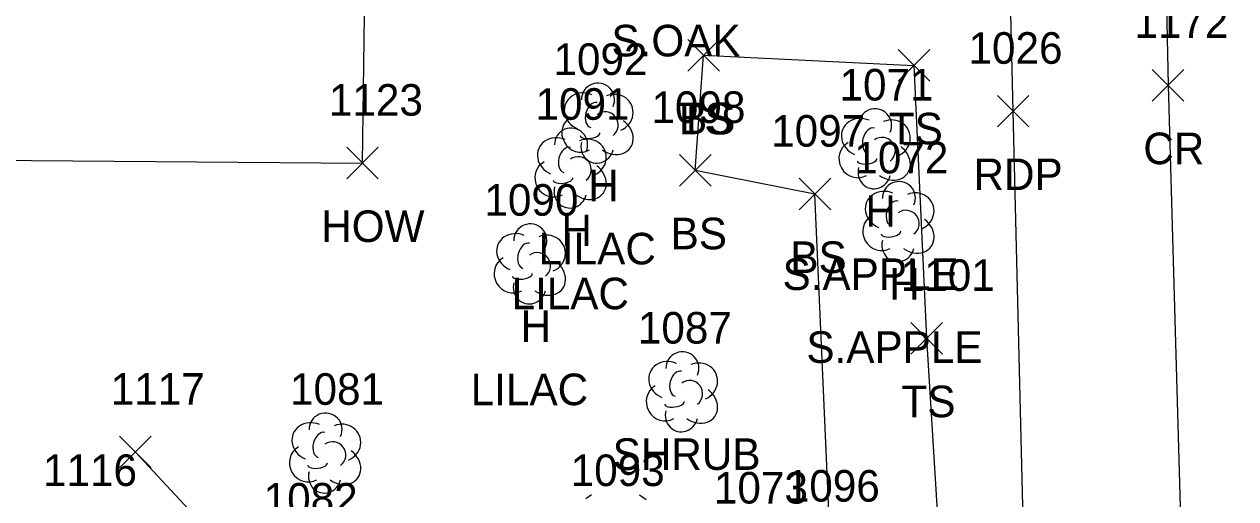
# Model space of a CAD drawing. Extents: x 1609623 to 1616187, y 756677 to 762826.
# Drawn here: x 1610552.4 to 1610629.1, y 761419.2 to 761449.2 of the extents above; entities that cross this region are included whole.
import ezdxf

# ---------------------------------------------------------------- set-up
doc = ezdxf.new("R2010")
doc.units = 0
for name, color, linetype in [('L_A', 7, 'Continuous'), ('L_C', 7, 'Continuous'), ('L_I', 7, 'Continuous'), ('L_TIC', 7, 'Continuous'), ('LBC', 7, 'Continuous'), ('LELB', 7, 'Continuous'), ('LSH', 7, 'Continuous'), ('LTC', 7, 'Continuous'), ('LTD', 7, 'Continuous'), ('P_A', 7, 'Continuous'), ('P_I', 7, 'Continuous'), ('P_TIC', 7, 'Continuous'), ('PET', 7, 'Continuous'), ('PRC', 7, 'Continuous')]:
    doc.layers.add(name, color=color, linetype=linetype)

msp = doc.modelspace()

# ---------------------------------------------------------------- linework, layer by layer
at = {"layer": 'L_TIC'}
for points in [[(1610594.408, 761446.245), (1610596.408, 761448.245)], [(1610596.408, 761446.245), (1610594.408, 761448.245)], [(1610594.408, 761446.245), (1610596.408, 761448.245)], [(1610596.408, 761446.245), (1610594.408, 761448.245)], [(1610607.722, 761445.603), (1610609.722, 761447.603)], [(1610609.722, 761445.603), (1610607.722, 761447.603)], [(1610572.816, 761439.42), (1610574.816, 761441.42)], [(1610574.816, 761439.42), (1610572.816, 761441.42)], [(1610593.878, 761438.959), (1610595.878, 761440.959)], [(1610595.878, 761438.959), (1610593.878, 761440.959)], [(1610601.455, 761437.458), (1610603.455, 761439.458)], [(1610603.455, 761437.458), (1610601.455, 761439.458)], [(1610608.524, 761428.323), (1610610.524, 761430.323)], [(1610610.524, 761428.323), (1610608.524, 761430.323)], [(1610558.441, 761421.114), (1610560.441, 761423.114)], [(1610560.441, 761421.114), (1610558.441, 761423.114)]]:
    msp.add_lwpolyline(points, dxfattribs=at)
at = {"layer": 'LBC'}
msp.add_lwpolyline([(1610544.984, 761440.641), (1610573.816, 761440.42), (1610574.182, 761466.993), (1610555.002, 761467.54), (1610555.534, 761478.683)], dxfattribs=at)
at = {"layer": 'LELB'}
for points in [[(1610595.408, 761447.245), (1610608.722, 761446.603), (1610609.524, 761429.323), (1610611.272, 761400.906), (1610611.999, 761372.747), (1610611.991, 761340.299), (1610612.489, 761301.493), (1610613.599, 761291.642), (1610617.432, 761248.111), (1610619.063, 761216.607), (1610613.007, 761244.85), (1610608.328, 761282.169), (1610599.672, 761300.772), (1610566.416, 761313.734)], [(1610596.168, 761387.633), (1610603.437, 761415.978), (1610602.455, 761438.458), (1610594.878, 761439.959), (1610595.408, 761447.245)], [(1610559.441, 761422.114), (1610573.999, 761406.454), (1610582.422, 761390.653)]]:
    msp.add_lwpolyline(points, dxfattribs=at)
at = {"layer": 'LSH'}
msp.add_line((1610594.018, 761425.986), (1610594.018, 761425.986), dxfattribs=at)
msp.add_line((1610594.018, 761425.986), (1610594.018, 761425.986), dxfattribs=at)
msp.add_arc((1610594.064, 761427.42), 1.047, 335.52715, 180.95627, dxfattribs=at)
for centre, major_axis, ratio, start_param, end_param in [((1610593.226, 761426.652), (1.21, -0.512), 0.895232, 1.570796, 4.712389), ((1610595.059, 761426.569), (-1.141, -0.483), 0.949671, 1.570796, 4.712389), ((1610593.809, 761426.444), (-0.208, -0.792), 0.645439, 3.141593, 6.283185), ((1610594.518, 761425.819), (-0.5, 0.667), 0.989748, 3.141593, 6.283185), ((1610592.934, 761425.277), (0.584, -1.042), 0.959034, 3.141593, 6.283185), ((1610595.018, 761425.153), (-1.09, 0.792), 0.841452, 1.570796, 4.712389), ((1610593.559, 761425.236), (-0.625, -0.083), 0.423636, 0, 3.141593), ((1610594.018, 761424.486), (0.265, 1.061), 0.942809, 1.570796, 4.712389)]:
    msp.add_ellipse(centre, major_axis=major_axis, ratio=ratio, start_param=start_param, end_param=end_param, dxfattribs=at)
at = {"layer": 'LTC'}
for p, q in [((1610587.961, 761419.171), (1610588.315, 761419.428)), ((1610591.359, 761419.411), (1610591.778, 761419.107))]:
    msp.add_line(p, q, dxfattribs=at)
at = {"layer": 'LTD'}
for p, q in [((1610588.674, 761443.001), (1610588.674, 761443.001)), ((1610588.674, 761443.001), (1610588.674, 761443.001)), ((1610606.214, 761441.381), (1610606.214, 761441.381)), ((1610606.214, 761441.381), (1610606.214, 761441.381)), ((1610586.972, 761440.16), (1610586.972, 761440.16)), ((1610586.972, 761440.16), (1610586.972, 761440.16)), ((1610607.722, 761436.764), (1610607.722, 761436.764)), ((1610607.722, 761436.764), (1610607.722, 761436.764)), ((1610584.39, 761434.086), (1610584.39, 761434.086)), ((1610584.39, 761434.086), (1610584.39, 761434.086)), ((1610571.433, 761422.109), (1610571.433, 761422.109)), ((1610571.433, 761422.109), (1610571.433, 761422.109))]:
    msp.add_line(p, q, dxfattribs=at)
for centre in [(1610588.721, 761444.435), (1610606.261, 761442.815), (1610587.019, 761441.594), (1610607.768, 761438.198), (1610584.437, 761435.52), (1610571.479, 761423.543)]:
    msp.add_arc(centre, 1.047, 335.52715, 180.95627, dxfattribs=at)
for centre, major_axis, ratio, start_param, end_param in [((1610587.883, 761443.668), (1.21, -0.512), 0.895232, 1.570796, 4.712389), ((1610589.716, 761443.585), (-1.141, -0.483), 0.949671, 1.570796, 4.712389), ((1610588.466, 761443.459), (-0.208, -0.792), 0.645439, 3.141593, 6.283185), ((1610589.175, 761442.834), (-0.5, 0.667), 0.989748, 3.141593, 6.283185), ((1610587.591, 761442.293), (0.584, -1.042), 0.959034, 3.141593, 6.283185), ((1610589.675, 761442.168), (-1.09, 0.792), 0.841452, 1.570796, 4.712389), ((1610605.423, 761442.047), (1.21, -0.512), 0.895232, 1.570796, 4.712389), ((1610607.256, 761441.964), (-1.141, -0.483), 0.949671, 1.570796, 4.712389), ((1610586.181, 761440.826), (1.21, -0.512), 0.895232, 1.570796, 4.712389), ((1610588.014, 761440.743), (-1.141, -0.483), 0.949671, 1.570796, 4.712389), ((1610588.216, 761442.251), (-0.625, -0.083), 0.423636, 0, 3.141593), ((1610606.006, 761441.839), (-0.208, -0.792), 0.645439, 3.141593, 6.283185), ((1610606.715, 761441.214), (-0.5, 0.667), 0.989748, 3.141593, 6.283185), ((1610586.764, 761440.618), (-0.208, -0.792), 0.645439, 3.141593, 6.283185), ((1610588.675, 761441.501), (0.265, 1.061), 0.942809, 1.570796, 4.712389), ((1610605.131, 761440.672), (0.584, -1.042), 0.959034, 3.141593, 6.283185), ((1610607.215, 761440.548), (-1.09, 0.792), 0.841452, 1.570796, 4.712389), ((1610587.472, 761439.993), (-0.5, 0.667), 0.989748, 3.141593, 6.283185), ((1610605.756, 761440.631), (-0.625, -0.083), 0.423636, 0, 3.141593), ((1610585.889, 761439.451), (0.584, -1.042), 0.959034, 3.141593, 6.283185), ((1610587.973, 761439.327), (-1.09, 0.792), 0.841452, 1.570796, 4.712389), ((1610606.215, 761439.881), (0.265, 1.061), 0.942809, 1.570796, 4.712389), ((1610586.514, 761439.41), (-0.625, -0.083), 0.423636, 0, 3.141593), ((1610586.973, 761438.66), (0.265, 1.061), 0.942809, 1.570796, 4.712389), ((1610606.93, 761437.431), (1.21, -0.512), 0.895232, 1.570796, 4.712389), ((1610608.763, 761437.348), (-1.141, -0.483), 0.949671, 1.570796, 4.712389), ((1610607.513, 761437.222), (-0.208, -0.792), 0.645439, 3.141593, 6.283185), ((1610608.222, 761436.598), (-0.5, 0.667), 0.989748, 3.141593, 6.283185), ((1610606.638, 761436.056), (0.584, -1.042), 0.959034, 3.141593, 6.283185), ((1610608.722, 761435.931), (-1.09, 0.792), 0.841452, 1.570796, 4.712389), ((1610583.598, 761434.752), (1.21, -0.512), 0.895232, 1.570796, 4.712389), ((1610585.432, 761434.669), (-1.141, -0.483), 0.949671, 1.570796, 4.712389), ((1610607.263, 761436.014), (-0.625, -0.083), 0.423636, 0, 3.141593), ((1610584.182, 761434.544), (-0.208, -0.792), 0.645439, 3.141593, 6.283185), ((1610607.722, 761435.264), (0.265, 1.061), 0.942809, 1.570796, 4.712389), ((1610583.307, 761433.377), (0.584, -1.042), 0.959034, 3.141593, 6.283185), ((1610584.89, 761433.919), (-0.5, 0.667), 0.989748, 3.141593, 6.283185), ((1610585.39, 761433.253), (-1.09, 0.792), 0.841452, 1.570796, 4.712389), ((1610583.932, 761433.336), (-0.625, -0.083), 0.423636, 0, 3.141593), ((1610584.39, 761432.586), (0.265, 1.061), 0.942809, 1.570796, 4.712389), ((1610570.641, 761422.776), (1.21, -0.512), 0.895232, 1.570796, 4.712389), ((1610572.474, 761422.693), (-1.141, -0.483), 0.949671, 1.570796, 4.712389), ((1610571.224, 761422.567), (-0.208, -0.792), 0.645439, 3.141593, 6.283185), ((1610571.933, 761421.942), (-0.5, 0.667), 0.989748, 3.141593, 6.283185), ((1610570.35, 761421.401), (0.584, -1.042), 0.959034, 3.141593, 6.283185), ((1610572.433, 761421.276), (-1.09, 0.792), 0.841452, 1.570796, 4.712389), ((1610570.975, 761421.359), (-0.625, -0.083), 0.423636, 0, 3.141593), ((1610571.433, 761420.609), (0.265, 1.061), 0.942809, 1.570796, 4.712389)]:
    msp.add_ellipse(centre, major_axis=major_axis, ratio=ratio, start_param=start_param, end_param=end_param, dxfattribs=at)
at = {"layer": 'P_TIC'}
for points in [[(1610623.803, 761444.349), (1610625.803, 761446.349)], [(1610625.803, 761444.349), (1610623.803, 761446.349)], [(1610614.001, 761442.708), (1610616.001, 761444.708)], [(1610616.001, 761442.708), (1610614.001, 761444.708)]]:
    msp.add_lwpolyline(points, dxfattribs=at)
at = {"layer": 'PET'}
msp.add_lwpolyline([(1610623.624, 761216.531), (1610618.72, 761291.922), (1610617.262, 761347.821), (1610616.065, 761400.586), (1610615.001, 761443.708), (1610614.378, 761469.339), (1610613.176, 761498.389)], dxfattribs=at)
at = {"layer": 'PRC'}
msp.add_lwpolyline([(1610615.344, 761821.258), (1610616.764, 761769.945), (1610617.486, 761726.015), (1610618.266, 761675.989), (1610618.81, 761645.854), (1610620.706, 761596.252), (1610622.201, 761543.733), (1610623.768, 761494.009), (1610624.803, 761445.349), (1610626.12, 761399.371), (1610627.458, 761348.429), (1610629.428, 761292.428), (1610633.696, 761219.48)], dxfattribs=at)

# ---------------------------------------------------------------- texts
at = {"layer": 'L_A'}
for s, p in [('TS', (1610593.818, 761442.245)), ('BS', (1610593.849, 761442.245)), ('TS', (1610607.132, 761441.603)), ('H', (1610588.108, 761438.001)), ('H', (1610605.648, 761436.381)), ('HOW', (1610571.202, 761435.42)), ('H', (1610586.405, 761435.16)), ('BS', (1610593.319, 761434.959)), ('BS', (1610600.896, 761433.458)), ('H', (1610607.155, 761431.764)), ('H', (1610583.823, 761429.086)), ('TS', (1610607.933, 761424.323)), ('SHRUB', (1610589.648, 761420.986))]:
    msp.add_text(s, height=2, dxfattribs=at).set_placement(p)
at = {"layer": 'L_C'}
for s, p in [('S.OAK', (1610589.572, 761447.174)), ('LILAC', (1610584.95, 761434.001)), ('S.APPLE', (1610600.403, 761432.381)), ('LILAC', (1610583.248, 761431.16)), ('S.APPLE', (1610601.911, 761427.764)), ('LILAC', (1610580.666, 761425.086))]:
    msp.add_text(s, height=2, dxfattribs=at).set_placement(p)
at = {"layer": 'L_I'}
for s, p in [('1092', (1610585.903, 761446.001)), ('1071', (1610604.01, 761444.381)), ('1123', (1610571.69, 761443.42)), ('1091', (1610584.768, 761443.16)), ('1098', (1610592.106, 761442.959)), ('1097', (1610599.683, 761441.458)), ('1072', (1610604.95, 761439.764)), ('1090', (1610581.532, 761437.086)), ('1101', (1610607.886, 761432.323)), ('1087', (1610591.246, 761428.986)), ('1117', (1610557.882, 761425.114)), ('1081', (1610569.228, 761425.109)), ('1116', (1610553.592, 761419.969)), ('1093', (1610586.994, 761419.963)), ('1073', (1610596.06, 761418.855)), ('1096', (1610600.61, 761418.978)), ('1082', (1610567.56, 761418.157))]:
    msp.add_text(s, height=2, dxfattribs=at).set_placement(p)
at = {"layer": 'P_A'}
for s, p in [('CR', (1610623.236, 761440.349)), ('RDP', (1610612.489, 761438.708))]:
    msp.add_text(s, height=2, dxfattribs=at).set_placement(p)
at = {"layer": 'P_I'}
for s, p in [('1172', (1610622.677, 761448.349)), ('1026', (1610612.174, 761446.708))]:
    msp.add_text(s, height=2, dxfattribs=at).set_placement(p)

doc.saveas('drawing.dxf')
